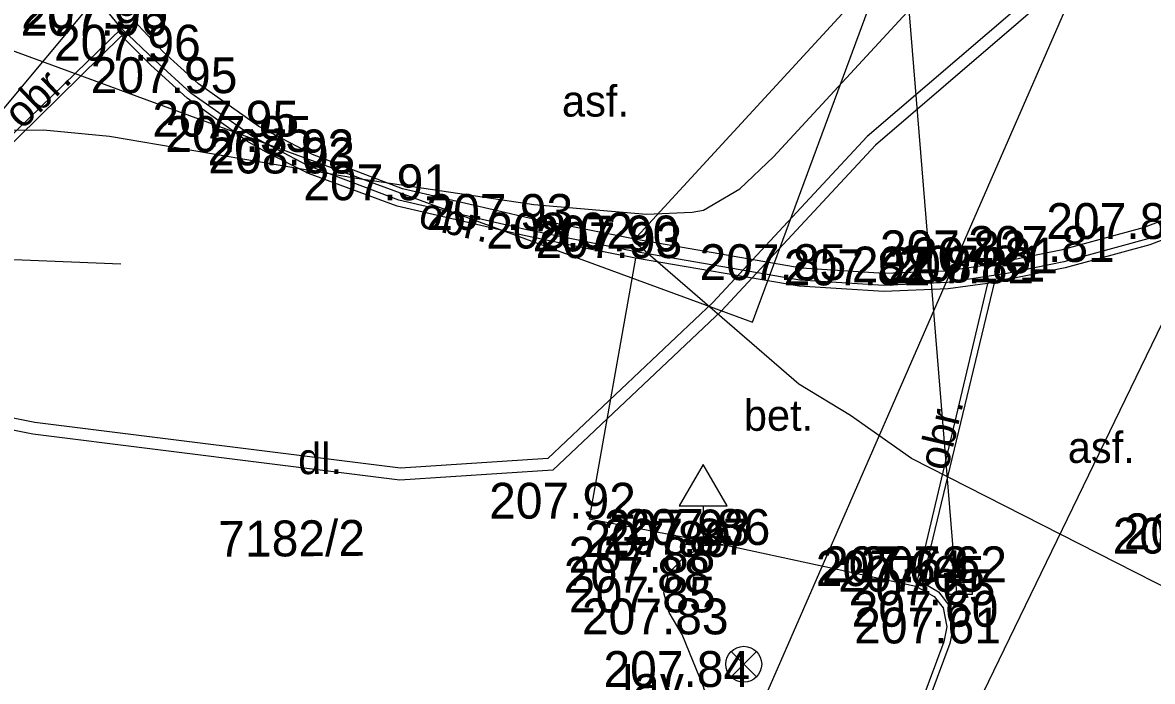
# Model space of a CAD drawing. Extents: x -524633 to -524336, y -1187893 to -1187683.
# Drawn here: x -524582.86 to -524559.24, y -1187820.09 to -1187806.31 of the extents above; entities that cross this region are included whole.
import ezdxf

# ---------------------------------------------------------------- set-up
doc = ezdxf.new("R2010")
doc.units = 0
for name, color, linetype in [('Hranice parcel', 7, 'Continuous'), ('Parcelní čísla', 7, 'Continuous'), ('Vrstva 1', 7, 'Continuous'), ('Vrstva 10', 7, 'Continuous'), ('Vrstva 11', 7, 'Continuous'), ('Vrstva 27', 7, 'Continuous'), ('Vrstva 3', 7, 'Continuous'), ('Vrstva 33', 7, 'Continuous'), ('Vrstva 34', 7, 'Continuous'), ('Vrstva 4', 7, 'Continuous'), ('Vrstva 40', 7, 'Continuous'), ('Vrstva 41', 7, 'Continuous'), ('Vrstva 52', 7, 'Continuous'), ('Vrstva 53', 7, 'Continuous'), ('Vrstva 55', 7, 'Continuous')]:
    doc.layers.add(name, color=color, linetype=linetype)

msp = doc.modelspace()

# ---------------------------------------------------------------- linework, layer by layer
at = {"layer": 'Hranice parcel'}
for points in [[(-524580.35, -1187850.24), (-524549.33, -1187779.18), (-524535.82, -1187753.93), (-524537.02, -1187750.93)], [(-524587.98, -1187805.09), (-524567.6, -1187812.58), (-524548.29, -1187760.37)], [(-524522.64, -1187765.24), (-524544.8, -1187788.23), (-524550.29, -1187795.7), (-524555.07, -1187804.42), (-524565.53, -1187826.01), (-524574.56, -1187855.86)]]:
    msp.add_lwpolyline(points, dxfattribs=at)
at = {"layer": 'Vrstva 1'}
for p, q in [((-524580.79, -1187806.44), (-524580.79, -1187806.44)), ((-524580.79, -1187806.59), (-524580.79, -1187806.59)), ((-524580.09, -1187807.11), (-524580.09, -1187807.11)), ((-524579.34, -1187807.79), (-524579.34, -1187807.79)), ((-524578.05, -1187808.7), (-524578.05, -1187808.7)), ((-524577.78, -1187809.02), (-524577.78, -1187809.02)), ((-524576.9, -1187809.3), (-524576.9, -1187809.3)), ((-524576.88, -1187809.47), (-524576.88, -1187809.47)), ((-524574.99, -1187810.03), (-524574.99, -1187810.03)), ((-524572.32, -1187810.65), (-524572.32, -1187810.65)), ((-524559.33, -1187810.84), (-524559.33, -1187810.84)), ((-524571.07, -1187811.04), (-524571.07, -1187811.04)), ((-524570.07, -1187811.1), (-524570.07, -1187811.1)), ((-524570.04, -1187811.24), (-524570.04, -1187811.24)), ((-524562.84, -1187811.41), (-524562.84, -1187811.41)), ((-524561.09, -1187811.32), (-524561.09, -1187811.32)), ((-524562.28, -1187811.56), (-524562.28, -1187811.56)), ((-524566.61, -1187811.7), (-524566.61, -1187811.7)), ((-524564.85, -1187811.81), (-524564.85, -1187811.81)), ((-524563.52, -1187811.75), (-524563.52, -1187811.75)), ((-524562.68, -1187811.77), (-524562.68, -1187811.77)), ((-524562.54, -1187811.73), (-524562.54, -1187811.73)), ((-524571.01, -1187816.69), (-524571.01, -1187816.69)), ((-524568.61, -1187817.25), (-524568.61, -1187817.25)), ((-524568.18, -1187817.24), (-524568.18, -1187817.24)), ((-524569.02, -1187817.49), (-524569.02, -1187817.49)), ((-524568.63, -1187817.44), (-524568.63, -1187817.44)), ((-524569.35, -1187817.82), (-524569.35, -1187817.82)), ((-524564.05, -1187818.02), (-524564.05, -1187818.02)), ((-524563.25, -1187818.02), (-524563.25, -1187818.02)), ((-524569.45, -1187818.24), (-524569.45, -1187818.24)), ((-524564.18, -1187818.1), (-524564.18, -1187818.1)), ((-524563.71, -1187818.22), (-524563.71, -1187818.22)), ((-524563.49, -1187818.5), (-524563.49, -1187818.5)), ((-524569.34, -1187818.65), (-524569.34, -1187818.65)), ((-524563.4, -1187818.95), (-524563.4, -1187818.95)), ((-524569.07, -1187819.11), (-524569.07, -1187819.11)), ((-524563.47, -1187819.3), (-524563.47, -1187819.3))]:
    msp.add_line(p, q, dxfattribs=at)
at = {"layer": 'Vrstva 10'}
for points in [[(-524580.79, -1187806.44), (-524582.419, -1187804.44), (-524583.259, -1187803.24), (-524583.979, -1187801.89), (-524584.359, -1187800.91), (-524584.86, -1187799.11), (-524585.139, -1187797.41), (-524585.209, -1187796.05), (-524585.2, -1187794.97), (-524584.999, -1187793.5), (-524584.54, -1187791.56), (-524584.17, -1187790.25)], [(-524550.109, -1187803.58), (-524553.579, -1187807.22), (-524555.624, -1187809.043), (-524557.179, -1187810.01), (-524559.329, -1187810.84), (-524561.09, -1187811.32), (-524562.28, -1187811.56), (-524563.52, -1187811.75), (-524564.849, -1187811.81), (-524566.609, -1187811.7), (-524570.069, -1187811.1), (-524572.319, -1187810.65), (-524574.99, -1187810.03), (-524576.899, -1187809.3), (-524578.049, -1187808.7), (-524579.34, -1187807.79), (-524580.09, -1187807.11), (-524580.79, -1187806.44)]]:
    msp.add_lwpolyline(points, dxfattribs=at)
at = {"layer": 'Vrstva 11'}
msp.add_line((-524580.79, -1187806.59), (-524584.589, -1187810.32), dxfattribs=at)
for points in [[(-524550.303, -1187803.392), (-524553.753, -1187807.04), (-524555.774, -1187808.842), (-524557.291, -1187809.785), (-524559.407, -1187810.602), (-524561.148, -1187811.077), (-524562.324, -1187811.314), (-524562.839, -1187811.41), (-524563.55, -1187811.51), (-524564.847, -1187811.56), (-524566.58, -1187811.451), (-524570.023, -1187810.854), (-524572.266, -1187810.406), (-524574.917, -1187809.79), (-524576.796, -1187809.072), (-524577.919, -1187808.486), (-524579.183, -1187807.595), (-524579.919, -1187806.927), (-524580.549, -1187806.26)], [(-524550.016, -1187803.67), (-524553.489, -1187807.314), (-524555.546, -1187809.148), (-524557.121, -1187810.127), (-524559.289, -1187810.964), (-524561.06, -1187811.447), (-524562.257, -1187811.688), (-524562.54, -1187811.73), (-524562.68, -1187811.77), (-524563.507, -1187811.88), (-524564.85, -1187811.94), (-524566.624, -1187811.829), (-524570.04, -1187811.24), (-524571.07, -1187811.04), (-524572.347, -1187810.777), (-524575.028, -1187810.155), (-524576.88, -1187809.47), (-524577.78, -1187809.02), (-524578.158, -1187808.803), (-524579.421, -1187807.892), (-524580.178, -1187807.205), (-524580.79, -1187806.59)], [(-524580.79, -1187806.44), (-524583.939, -1187809.49)], [(-524570.04, -1187811.24), (-524571.009, -1187816.69), (-524568.18, -1187817.24), (-524564.18, -1187818.1)], [(-524562.68, -1187811.77), (-524564.18, -1187818.1), (-524563.797, -1187818.32), (-524563.61, -1187818.556), (-524563.532, -1187818.95), (-524563.595, -1187819.264), (-524568.591, -1187832.674), (-524569.493, -1187835.073), (-524572.367, -1187842.718), (-524571.99, -1187843.01), (-524571.05, -1187843.65), (-524568.395, -1187845.551), (-524568.06, -1187845.502), (-524562.536, -1187844.006), (-524562.569, -1187843.88)], [(-524562.54, -1187811.73), (-524564.049, -1187818.02), (-524563.71, -1187818.22), (-524563.489, -1187818.5), (-524563.399, -1187818.95), (-524563.47, -1187819.3), (-524568.469, -1187832.72), (-524572.21, -1187842.67), (-524568.369, -1187845.41), (-524568.06, -1187845.36), (-524562.569, -1187843.88)], [(-524569.07, -1187819.11), (-524569.339, -1187818.65), (-524569.45, -1187818.24), (-524569.349, -1187817.82), (-524569.02, -1187817.49), (-524568.61, -1187817.25), (-524568.18, -1187817.24)], [(-524571.99, -1187843.01), (-524572.58, -1187844.61), (-524578.969, -1187839.8), (-524577.87, -1187833.69), (-524576.57, -1187833.66), (-524575.68, -1187833.49), (-524574.809, -1187833.25), (-524573.78, -1187832.87), (-524572.81, -1187832.35), (-524571.89, -1187831.74), (-524570.779, -1187830.73), (-524570.08, -1187829.86), (-524569.23, -1187828.47), (-524568.57, -1187827.08), (-524568.199, -1187825.78), (-524567.989, -1187824.27), (-524568.029, -1187822.95), (-524568.219, -1187821.6), (-524568.619, -1187820.21), (-524569.07, -1187819.11)]]:
    msp.add_lwpolyline(points, dxfattribs=at)
at = {"layer": 'Vrstva 27'}
msp.add_line((-524563.5, -1187818.02), (-524563, -1187818.02), dxfattribs=at)
msp.add_lwpolyline([(-524563.5, -1187818.27), (-524563, -1187818.27), (-524563, -1187817.77), (-524563.5, -1187817.77)], close=True, dxfattribs=at)
at = {"layer": 'Vrstva 33'}
for p, q in [((-524568.045, -1187820), (-524567.515, -1187819.47)), ((-524568.045, -1187819.47), (-524567.515, -1187820))]:
    msp.add_line(p, q, dxfattribs=at)
msp.add_circle((-524567.78, -1187819.735), 0.375, dxfattribs=at)
at = {"layer": 'Vrstva 34'}
for p, q in [((-524568.63, -1187816.422), (-524568.63, -1187817.44)), ((-524568.88, -1187817.44), (-524568.38, -1187817.44))]:
    msp.add_line(p, q, dxfattribs=at)
msp.add_lwpolyline([(-524569.13, -1187816.422), (-524568.13, -1187816.422), (-524568.63, -1187815.556)], close=True, dxfattribs=at)
at = {"layer": 'Vrstva 52'}
for points in [[(-524519.66, -1187780.8), (-524520.03, -1187780.68), (-524522.13, -1187778.25), (-524523.23, -1187776.15), (-524527.13, -1187770.84), (-524527.38, -1187770.79), (-524527.58, -1187770.85), (-524528.03, -1187771.24), (-524542.13, -1187785.97), (-524549.4, -1187793.54), (-524554.08, -1187798.54), (-524557.736, -1187802.445), (-524558.69, -1187802.95), (-524559.6, -1187803.25), (-524560.59, -1187803.9), (-524560.883, -1187804.457), (-524561.184, -1187804.99), (-524561.439, -1187805.468), (-524565.196, -1187808.697), (-524568.424, -1187812.167), (-524571.876, -1187815.434), (-524574.96, -1187815.631), (-524582.602, -1187814.676), (-524588.605, -1187813.474)], [(-524583.93, -1187808.57), (-524582.42, -1187808.56), (-524581.04, -1187808.69), (-524575.88, -1187809.57), (-524572.17, -1187810.12), (-524569.81, -1187810.32), (-524568.86, -1187810.28), (-524568.62, -1187810.24), (-524567.86, -1187809.79), (-524567.16, -1187809.12), (-524564.11, -1187805.82), (-524562.45, -1187803.99), (-524561.59, -1187802.82), (-524561.25, -1187801.73), (-524557.13, -1187797.88), (-524552.13, -1187792.59), (-524549.07, -1187789.37), (-524546.96, -1187787.21), (-524543.69, -1187783.96), (-524541.3, -1187781.22)], [(-524583.93, -1187808.57), (-524582.42, -1187808.56), (-524581.04, -1187808.69), (-524575.88, -1187809.57), (-524572.17, -1187810.12), (-524569.81, -1187810.32), (-524568.86, -1187810.28), (-524568.62, -1187810.24), (-524567.86, -1187809.79), (-524567.16, -1187809.12), (-524564.11, -1187805.82), (-524562.45, -1187803.99), (-524561.59, -1187802.82), (-524561.25, -1187801.73), (-524557.13, -1187797.88), (-524552.13, -1187792.59), (-524549.07, -1187789.37), (-524546.96, -1187787.21), (-524543.69, -1187783.96), (-524541.3, -1187781.22)], [(-524561.344, -1187803.955), (-524561.158, -1187804.072), (-524561.105, -1187804.363), (-524560.563, -1187805.046), (-524565.022, -1187808.878), (-524568.246, -1187812.343), (-524571.77, -1187815.678), (-524574.968, -1187815.882), (-524582.642, -1187814.923), (-524588.661, -1187813.718), (-524593.294, -1187812.534), (-524595.823, -1187812.509), (-524597.459, -1187812.746), (-524604.971, -1187810.656)]]:
    msp.add_lwpolyline(points, dxfattribs=at)
at = {"layer": 'Vrstva 53'}
msp.add_lwpolyline([(-524554.4, -1187816.53), (-524555.47, -1187816.86), (-524554.98, -1187818.2), (-524558.03, -1187818.61), (-524564.27, -1187815.43), (-524565.55, -1187814.53), (-524566.63, -1187813.88), (-524570.09, -1187810.88), (-524552.62, -1187791.89), (-524542.18, -1187780.94), (-524533.44, -1187771.54), (-524532.07, -1187769.81), (-524527.29, -1187764.61)], dxfattribs=at)
at = {"layer": 'Vrstva 55'}
for p, q in [((-524585.8, -1187811.16), (-524537.22, -1187752.94)), ((-524564.874, -1187799.347), (-524563.33, -1187818.25)), ((-524585.8, -1187811.16), (-524580.804, -1187811.357))]:
    msp.add_line(p, q, dxfattribs=at)

# ---------------------------------------------------------------- texts
at = {"layer": 'Parcelní čísla'}
msp.add_text('7182/2', height=0.75, rotation=0.4246, dxfattribs=at).set_placement((-524578.764, -1187817.489))
at = {"layer": 'Vrstva 3'}
for s, p in [('207.95', (-524580.145, -1187808.7)), ('207.91', (-524576.99, -1187810.03)), ('207.90', (-524572.194, -1187811.1)), ('207.81', (-524565.52, -1187811.75)), ('207.92', (-524573.104, -1187816.69)), ('207.65', (-524560.065, -1187817.42)), ('207.62', (-524565.344, -1187818.02)), ('207.61', (-524565.47, -1187819.3)), ('207.84', (-524570.714, -1187820.21))]:
    msp.add_text(s, height=0.75, dxfattribs=at).set_placement(p)
at = {"layer": 'Vrstva 4'}
for s, p in [('207.95', (-524582.885, -1187806.44)), ('207.96', (-524582.901, -1187806.59)), ('207.96', (-524582.201, -1187807.11)), ('207.95', (-524581.435, -1187807.79)), ('207.95', (-524579.875, -1187809.02)), ('207.92', (-524578.994, -1187809.3)), ('208.03', (-524578.974, -1187809.47)), ('207.93', (-524574.414, -1187810.65)), ('207.80', (-524561.454, -1187810.84)), ('208.02', (-524573.164, -1187811.04)), ('207.93', (-524572.134, -1187811.24)), ('207.82', (-524564.934, -1187811.41)), ('207.81', (-524563.09, -1187811.32)), ('207.85', (-524568.705, -1187811.7)), ('207.81', (-524564.28, -1187811.56)), ('207.82', (-524566.944, -1187811.81)), ('207.82', (-524564.774, -1187811.77)), ('207.81', (-524564.54, -1187811.73)), ('207.93', (-524570.704, -1187817.25)), ('207.86', (-524570.291, -1187817.24)), ('207.69', (-524559.834, -1187817.33)), ('207.89', (-524571.114, -1187817.49)), ('207.87', (-524570.724, -1187817.44)), ('207.88', (-524571.444, -1187817.82)), ('207.63', (-524566.144, -1187818.02)), ('207.88', (-524571.544, -1187818.24)), ('207.64', (-524566.274, -1187818.1)), ('207.65', (-524565.805, -1187818.22)), ('207.65', (-524565.585, -1187818.5)), ('207.85', (-524571.435, -1187818.65)), ('207.60', (-524565.524, -1187818.95)), ('207.83', (-524571.164, -1187819.11))]:
    msp.add_text(s, height=0.75, dxfattribs=at).set_placement(p)
at = {"layer": 'Vrstva 40'}
for rotation, p in [(44.0828, (-524582.87, -1187808.572)), (346.9306, (-524574.61, -1187810.583)), (76.6687, (-524563.524, -1187815.711))]:
    msp.add_text('obr.', height=0.65, rotation=rotation, dxfattribs=at).set_placement(p)
for s, p in [('asf.', (-524571.581, -1187808.28)), ('bet.', (-524567.778, -1187814.852)), ('asf.', (-524561.005, -1187815.524)), ('dl.', (-524577.097, -1187815.759))]:
    msp.add_text(s, height=0.65, dxfattribs=at).set_placement(p)
at = {"layer": 'Vrstva 41'}
msp.add_text('lav.', height=0.75, dxfattribs=at).set_placement((-524570.314, -1187820.518))

doc.saveas('drawing.dxf')
